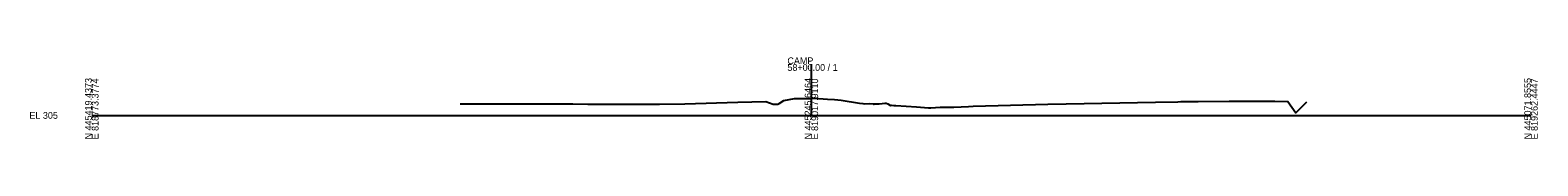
# Model space of a CAD drawing. Extents: x -26 to 603, y -10 to 2524.
# Drawn here: x -26 to 603, y 2490 to 2524 of the extents above; entities that cross this region are included whole.
import ezdxf

# ---------------------------------------------------------------- set-up
doc = ezdxf.new("R2010")
doc.units = 0
doc.layers.add('DESIGN - SHEET - Light Grid', color=7, linetype='Continuous')
doc.layers.add('SURVEY - GROUND - Top of Ground', color=7, linetype='Continuous')

msp = doc.modelspace()

# ---------------------------------------------------------------- linework, layer by layer
at = {"layer": 'DESIGN - SHEET - Light Grid'}
for p, q in [((300, 2500), (300, 2521.38)), ((0, 2500), (300, 2500)), ((300, 2500), (600, 2500))]:
    msp.add_line(p, q, dxfattribs=at)
at = {"layer": 'SURVEY - GROUND - Top of Ground'}
msp.add_lwpolyline([(153.55, 2504.81), (165.18, 2504.81), (180.48, 2504.89), (200.54, 2504.79), (206.74, 2504.68), (236.73, 2504.73), (247.25, 2504.79), (269.39, 2505.5), (280.94, 2505.87), (284.04, 2504.73), (286.04, 2504.74), (286.53, 2505.01), (288.54, 2506.17), (290.68, 2506.59), (293, 2507.08), (297.62, 2507.1), (300, 2507.12), (301.19, 2507.13), (306.74, 2506.8), (309.66, 2506.66), (312.44, 2506.4), (320.1, 2505.1), (321.38, 2504.93), (322.2, 2504.83), (324.25, 2504.94), (325.86, 2504.83), (326.05, 2504.6), (326.5, 2504.78), (328.24, 2504.78), (330.77, 2505.15), (331.15, 2505.05), (331.88, 2504.86), (333, 2504.19), (333.5, 2504.22), (334.35, 2504.19), (335.19, 2504.13), (343.82, 2503.55), (348.87, 2503.12), (349.8, 2503.19), (353.63, 2503.49), (359.42, 2503.48), (365.48, 2503.77), (367.41, 2503.89), (398.63, 2504.66), (406.14, 2504.86), (443.39, 2505.49), (452.81, 2505.71), (454, 2505.74), (455.48, 2505.75), (456.77, 2505.75), (458.14, 2505.75), (459.61, 2505.75), (461.18, 2505.75), (474.09, 2505.94), (493.13, 2505.95), (498.67, 2505.83), (501.96, 2501.05), (506.5, 2505.64)], dxfattribs=at)

# ---------------------------------------------------------------- texts
at = {"layer": 'DESIGN - SHEET - Light Grid'}
for s, p in [('58+00.00 / 1', (290, 2518.58)), ('CAMP', (290, 2521.38)), ('EL 305', (-26, 2498.6))]:
    msp.add_text(s, height=2.8, dxfattribs=at).set_placement(p)
for s, p in [('N 445419.4373', (0, 2490)), ('E 818773.3774', (2.8, 2490)), ('N 445245.6464', (300, 2490)), ('E 819017.9110', (302.8, 2490)), ('N 445071.8555', (600, 2490)), ('E 819262.4447', (602.8, 2490))]:
    msp.add_text(s, height=2.8, rotation=90, dxfattribs=at).set_placement(p)

doc.saveas('drawing.dxf')
